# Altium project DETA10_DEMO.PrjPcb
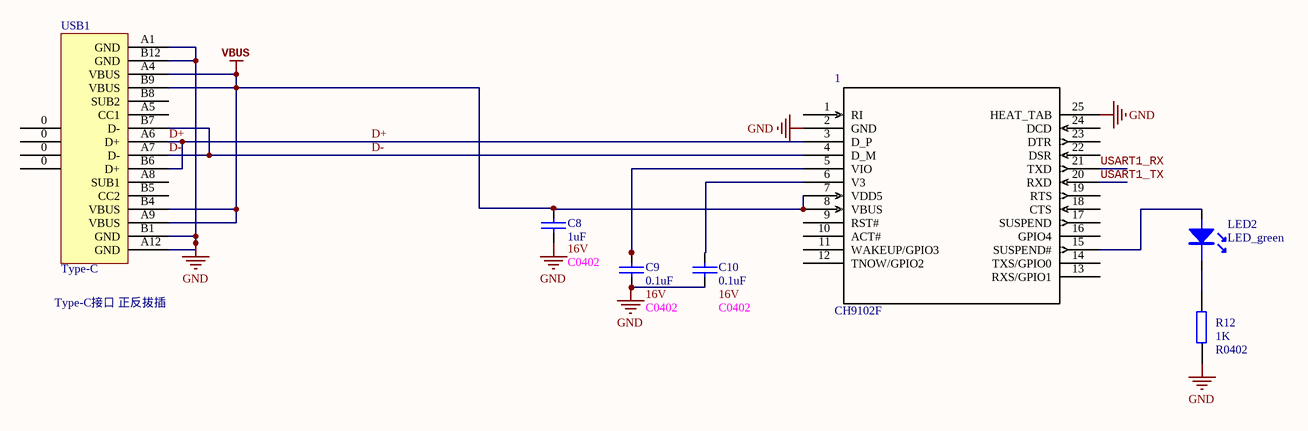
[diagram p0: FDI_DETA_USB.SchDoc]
2 sheets, 12 parts. Net scope: global (net labels, ports and power ports of the same name join across sheets).
Board file: DETA10_EVB_DEMO20230104.PcbDoc
Sheets:
  FDI_DETA_USB.SchDoc
  FDI_DETA_LDO.SchDoc

## Sheet FDI_DETA_USB.SchDoc
size A4

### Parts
1  CH9102F  [QFN24_4X4]
C8  1uF  [C0402]
C9  0.1uF  [C0402]
C10  0.1uF  [C0402]
LED2  LED_green  [LED_0603_GREEN]
R12  1K  [RES0402]
USB1  Type-C  [Type-C_Socket_16P]

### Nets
GND: 1.2(GND) 1.25(HEAT_TAB) C8.1 C9.1 C10.1 R12.2 USB1.A1(GND) USB1.A12(GND) USB1.B1(GND) USB1.B12(GND)
VBUS: 1.7(VDD5) 1.8(VBUS) C8.2 USB1.A4(VBUS) USB1.A9(VBUS) USB1.B4(VBUS) USB1.B9(VBUS)
D+: 1.3(D_P) USB1.A6(D+) USB1.B6(D+)
D-: 1.4(D_M) USB1.A7(D-) USB1.B7(D-)
USART1_RX: 1.21(TXD)
USART1_TX: 1.20(RXD)
Net1_5: 1.5(VIO) C9.2
Net1_6: 1.6(V3) C10.2
Net1_15: 1.15(SUSPEND#) LED2.1
NetLED2_2: LED2.2 R12.1

Not connected (* = marked no-connect by the designer): 1 1(RI) 9(RST#) 10(ACT#) 11(WAKEUP/GPIO3) 12(TNOW/GPIO2) 13(RXS/GPIO1) 14(TXS/GPIO0) 16(GPIO4) 17(SUSPEND) 18(CTS) 19(RTS) 22(DSR) 23(DTR) 24(DCD); USB1 0 A5(CC1) A8(SUB1) B5(CC2) B8(SUB2)

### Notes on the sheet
- (near USB1) Type-C接口 正反拔插

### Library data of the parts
1 = CH9102F: Imported
C8-C10 = C1
LED2 = LED
R12 = R
USB1 = Type-C Socket: USB 3.1  单排16PIN四脚插板(L=7.35) 一体式MD

## Sheet FDI_DETA_LDO.SchDoc
size A4
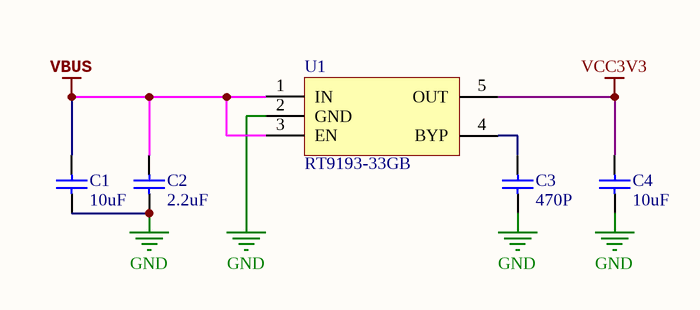
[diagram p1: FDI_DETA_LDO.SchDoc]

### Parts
C1  10uF  [C0603]
C2  2.2uF  [C0402]
C3  470P  [C0402]
C4  10uF  [C0603]
U1  RT9193-33GB  [SOT23-5]

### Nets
GND: C1.1 C2.1 C3.1 C4.1 U1.2(GND)
VBUS: C1.2 C2.2 U1.1(IN) U1.3(EN)
VCC3V3: C4.2 U1.5(OUT)
NetC3_2: C3.2 U1.4(BYP)

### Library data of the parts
C1-C4 = Cap1: 贴片瓷介电容
U1 = MIC5205: 150mA Low-Noise LDO Regulator

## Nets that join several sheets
GND: FDI_DETA_USB (10 pins), FDI_DETA_LDO (5 pins)
VBUS: FDI_DETA_USB (7 pins), FDI_DETA_LDO (C1.2 C2.2 U1.1 U1.3)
